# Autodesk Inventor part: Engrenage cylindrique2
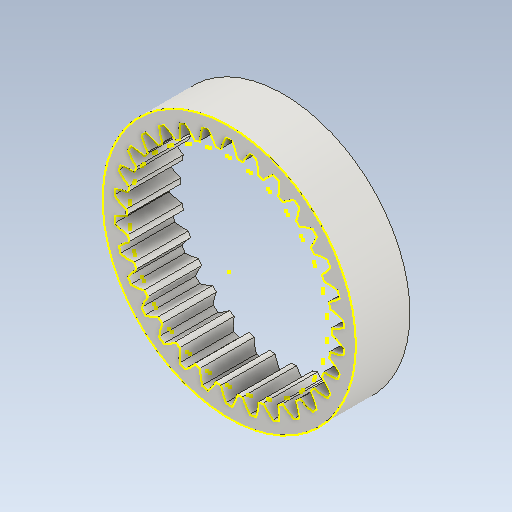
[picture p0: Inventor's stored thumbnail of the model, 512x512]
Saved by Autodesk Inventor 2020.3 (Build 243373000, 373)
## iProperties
CustomPartVersion: 1
Created: 2020-11
Part Number: Engrenage cylindrique2
Material: Steel
Document SubType Name: Modeling
Designer: ficho
Categories: <?xml version="1.0" encoding="UTF-16"?> <MemberInstance><Categories><FamilyTemplate><FamilyTemplateParameter ValueType="xs:double" Id="1" ObjectReferenceKey="da
Density: 7.85 g/cm^3
Appearance: Steel
Mass: 4.24814 g
Surface Area: 11.1433 cm^2
Volume: 0.541165 cm^3
d16: 6,500 mm
d17: 0,000 mm
d45: 0,000 mm
d47: 6,500 mm
d50: 0,000 mm
d51: 0,000 mm
d52: 6,500 mm
Author: ficho
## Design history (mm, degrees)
sketch "Sketch1"
  geometry: C1 r 11.619 at (0, 0)
  constraints: 1 centre point
  dimensions: "d0" = 23.2375 diameter of C1 (= 1.1 x da_df)
extrude "Extrusion1" new body sketch "Sketch1" distance "d1" = 5 (= da_b); taper "d2" = 0 deg
workplane "Work Plane2"
sketch "Sketch2"
  geometry: C1 r 11.619 at (0, 0) reference; C2 r 9.75 at (0, 0)
  constraints: 1 centre point, 1 coincident
  dimensions: "d3" = 19.5 diameter of C2 (= da_dw)
feature "Diamètre primitif" sketch "Sketch2" dims "d4" = 10, "d5" = 0
workplane "Work Plane8"
workplane "Work Plane9"
feature "Engrenage cylindrique" dims "da_b" = 5, "da_d" = 19.5, "da_z" = 300, "da_aw" = 6.5, "da_da" = 18.85573, "da_df" = 21.125, "da_dw" = 19.5, "da_z2" = 100, "da_beta" = 0, "da_lefttooth" = 0, "da_righttooth" = 0, "da_straighttooth" = 10
sketch "Esquisse3"
  geometry: C1 r 11.619 at (0, 0) reference; A1 r 4.705 centre (-2.024, -8.864) between (2.466, -10.271) and (2.678, -9.04) reference; A2 r 10.562 centre (0, 0) between (1.925, -10.386) and (2.466, -10.271) reference; A3 r 4.705 centre (5.455, -7.274) between (1.231, -9.347) and (1.925, -10.386) reference; A4 r 9.428 centre (0, 0) between (0.74, -9.399) and (1.231, -9.347) reference; A5 r 4.705 centre (-3.823, -8.25) between (0.276, -10.559) and (0.74, -9.399) reference; A6 r 10.563 centre (0, 0) between (-0.276, -10.559) and (0.276, -10.559) reference; A7 r 4.705 centre (3.823, -8.25) between (-0.74, -9.399) and (-0.276, -10.559) reference; A8 r 9.428 centre (0, 0) between (-1.231, -9.347) and (-0.74, -9.399) reference; A9 r 4.705 centre (-5.455, -7.274) between (-1.925, -10.386) and (-1.231, -9.347) reference; A10 r 10.563 centre (0, 0) between (-2.466, -10.271) and (-1.925, -10.386) reference; A11 r 4.705 centre (2.024, -8.864) between (-2.678, -9.04) and (-2.466, -10.271) reference; A12 r 9.428 centre (0, 0) between (-3.147, -8.887) and (-2.678, -9.04) reference; A13 r 4.705 centre (-6.848, -5.981) between (-4.042, -9.758) and (-3.147, -8.887) reference; A14 r 10.562 centre (0, 0) between (-4.547, -9.534) and (-4.042, -9.758) reference; A15 r 4.705 centre (0.137, -9.091) between (-4.499, -8.285) and (-4.547, -9.534) reference; A16 r 9.428 centre (0, 0) between (-4.926, -8.039) and (-4.499, -8.285) reference; A17 r 4.705 centre (-7.942, -4.427) between (-5.983, -8.705) and (-4.926, -8.039) reference; A18 r 10.563 centre (0, 0) between (-6.43, -8.38) and (-5.983, -8.705) reference; A19 r 4.705 centre (-1.756, -8.921) between (-6.123, -7.169) and (-6.43, -8.38) reference; A20 r 9.428 centre (0, 0) between (-6.49, -6.839) and (-6.123, -7.169) reference; A21 r 4.705 centre (-8.689, -2.679) between (-7.662, -7.271) and (-6.49, -6.839) reference; A22 r 10.563 centre (0, 0) between (-8.032, -6.86) and (-7.662, -7.271) reference; A23 r 4.705 centre (-3.573, -8.361) between (-7.48, -5.739) and (-8.032, -6.86) reference; A24 r 9.428 centre (0, 0) between (-7.77, -5.34) and (-7.48, -5.739) reference; A25 r 4.705 centre (-9.056, -0.814) between (-9.006, -5.519) and (-7.77, -5.34) reference; A26 r 10.562 centre (0, 0) between (-9.283, -5.04) and (-9.006, -5.519) reference; A27 r 4.705 centre (-5.233, -7.435) between (-8.509, -4.059) and (-9.283, -5.04) reference; A28 r 9.428 centre (0, 0) between (-8.71, -3.608) and (-8.509, -4.059) reference; A29 r 4.705 centre (-9.027, 1.087) between (-9.957, -3.526) and (-8.71, -3.608) reference; A30 r 10.562 centre (0, 0) between (-10.128, -3) and (-9.957, -3.526) reference; A31 r 4.705 centre (-6.664, -6.185) between (-9.167, -2.201) and (-10.128, -3) reference; A32 r 9.428 centre (0, 0) between (-9.27, -1.718) and (-9.167, -2.201) reference; A33 r 4.705 centre (-8.604, 2.94) between (-10.472, -1.379) and (-9.27, -1.718) reference; A34 r 10.562 centre (0, 0) between (-10.53, -0.829) and (-10.472, -1.379) reference; A35 r 4.705 centre (-7.805, -4.664) between (-9.425, -0.247) and (-10.53, -0.829) reference; A36 r 9.428 centre (0, 0) between (-9.425, 0.247) and (-9.425, -0.247) reference; A37 r 4.705 centre (-7.805, 4.664) between (-10.53, 0.829) and (-9.425, 0.247) reference; A38 r 10.563 centre (0, 0) between (-10.472, 1.379) and (-10.53, 0.829) reference; A39 r 4.705 centre (-8.604, -2.94) between (-9.27, 1.718) and (-10.472, 1.379) reference; A40 r 9.428 centre (0, 0) between (-9.167, 2.201) and (-9.27, 1.718) reference; A41 r 4.705 centre (-6.664, 6.185) between (-10.128, 3) and (-9.167, 2.201) reference; A42 r 10.563 centre (0, 0) between (-9.957, 3.526) and (-10.128, 3) reference; A43 r 4.705 centre (-9.027, -1.087) between (-8.71, 3.608) and (-9.957, 3.526) reference; A44 r 9.428 centre (0, 0) between (-8.509, 4.059) and (-8.71, 3.608) reference; A45 r 4.705 centre (-5.233, 7.435) between (-9.283, 5.04) and (-8.509, 4.059) reference; A46 r 10.563 centre (0, 0) between (-9.006, 5.519) and (-9.283, 5.04) reference; A47 r 4.705 centre (-9.056, 0.814) between (-7.77, 5.34) and (-9.006, 5.519) reference; A48 r 9.428 centre (0, 0) between (-7.48, 5.739) and (-7.77, 5.34) reference; A49 r 4.705 centre (-3.573, 8.361) between (-8.032, 6.86) and (-7.48, 5.739) reference; A50 r 10.563 centre (0, 0) between (-7.662, 7.271) and (-8.032, 6.86) reference; A51 r 4.705 centre (-8.689, 2.679) between (-6.49, 6.839) and (-7.662, 7.271) reference; A52 r 9.428 centre (0, 0) between (-6.123, 7.169) and (-6.49, 6.839) reference; A53 r 4.705 centre (-1.756, 8.921) between (-6.43, 8.38) and (-6.123, 7.169) reference; A54 r 10.563 centre (0, 0) between (-5.983, 8.705) and (-6.43, 8.38) reference; A55 r 4.705 centre (-7.942, 4.427) between (-4.926, 8.039) and (-5.983, 8.705) reference; A56 r 9.428 centre (0, 0) between (-4.499, 8.285) and (-4.926, 8.039) reference; A57 r 4.705 centre (0.137, 9.091) between (-4.547, 9.534) and (-4.499, 8.285) reference; A58 r 10.563 centre (0, 0) between (-4.042, 9.758) and (-4.547, 9.534) reference; A59 r 4.705 centre (-6.848, 5.981) between (-3.147, 8.887) and (-4.042, 9.758) reference; A60 r 9.428 centre (0, 0) between (-2.678, 9.04) and (-3.147, 8.887) reference; A61 r 4.705 centre (2.024, 8.864) between (-2.466, 10.271) and (-2.678, 9.04) reference; A62 r 10.562 centre (0, 0) between (-1.925, 10.386) and (-2.466, 10.271) reference; A63 r 4.705 centre (-5.455, 7.274) between (-1.231, 9.347) and (-1.925, 10.386) reference; A64 r 9.428 centre (0, 0) between (-0.74, 9.399) and (-1.231, 9.347) reference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; 1 further point
  node "Boucle projetée1"
body "Solid1"
body "Srf1"
other parameters: "d16" = 6.5 (= da_aw), "d17" = 0, "d34" = 6 deg (computed from da_z), "d39" = 0, "d45" = 0, "d47" = 6.5 (= da_aw), "d50" = 0, "d51" = 0, "d52" = 6.5 (= da_aw)
